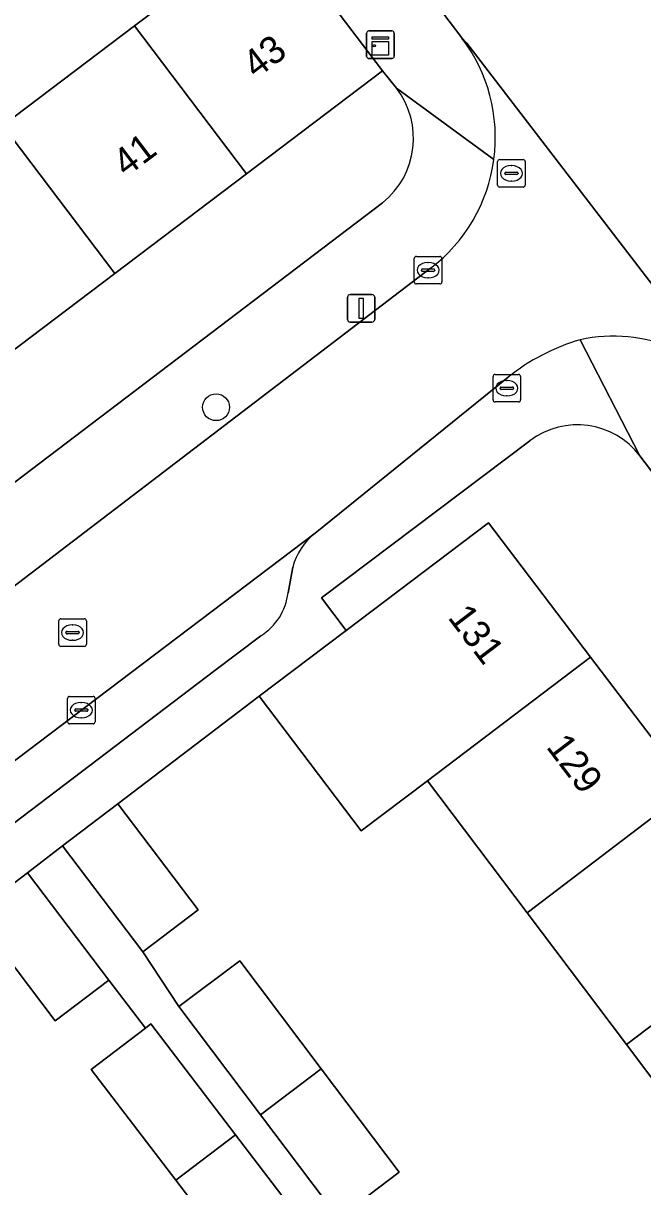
# Model space of a CAD drawing. Extents: x 160030 to 160839, y 385325 to 386450.
# Drawn here: x 160342.79 to 160365.28, y 385850.63 to 385892.89 of the extents above; entities that cross this region are included whole.
import ezdxf

# ---------------------------------------------------------------- set-up
doc = ezdxf.new("R2010")
doc.units = 0
for name, color, linetype in [('IMGEO_Boom', 7, 'Continuous'), ('IMGEO_Brandkraan', 7, 'Continuous'), ('IMGEO_Erf', 7, 'Continuous'), ('IMGEO_Kast', 7, 'Continuous'), ('IMGEO_Kolk', 7, 'Continuous'), ('IMGEO_Lichtmast', 7, 'Continuous'), ('IMGEO_Muur', 7, 'Continuous'), ('IMGEO_Pand', 7, 'Continuous'), ('IMGEO_Pand_nummerreeks', 7, 'Continuous'), ('IMGEO_Parkeervlak_open', 7, 'Continuous'), ('IMGEO_Rijbaan_lokaal_open', 7, 'Continuous'), ('IMGEO_Rioolput', 7, 'Continuous'), ('IMGEO_Voetpad_open', 7, 'Continuous')]:
    doc.layers.add(name, color=color, linetype=linetype)

msp = doc.modelspace()

# ---------------------------------------------------------------- linework, layer by layer
at = {"layer": 'IMGEO_Boom'}
msp.add_circle((160349.794, 385878.947), 0.489, dxfattribs=at)
at = {"layer": 'IMGEO_Brandkraan'}
for p, q in [((160360.014, 385887.015), (160360.014, 385887.867)), ((160360.089, 385887.941), (160360.941, 385887.941)), ((160360.502, 385887.721), (160360.527, 385887.721)), ((160361.015, 385887.867), (160361.015, 385887.015)), ((160360.273, 385887.435), (160360.273, 385887.447)), ((160360.711, 385887.398), (160360.313, 385887.398)), ((160360.316, 385887.484), (160360.714, 385887.484)), ((160360.525, 385887.161), (160360.5, 385887.161)), ((160360.757, 385887.447), (160360.757, 385887.435)), ((160360.941, 385886.941), (160360.089, 385886.941))]:
    msp.add_line(p, q, dxfattribs=at)
for points in [[(160360.014, 385887.015), (160360.014, 385887.867)], [(160360.089, 385887.941), (160360.941, 385887.941)], [(160361.015, 385887.867), (160361.015, 385887.015)], [(160360.941, 385886.941), (160360.089, 385886.941)]]:
    msp.add_lwpolyline(points, dxfattribs=at)
for centre, radius, start, end in [((160360.091, 385887.865), 0.0765, 91.552, 178.448), ((160360.091, 385887.865), 0.0765, 91.552, 178.448), ((160360.939, 385887.865), 0.0765, 1.552, 88.448), ((160360.939, 385887.865), 0.0765, 1.552, 88.448), ((160360.313, 385887.444), 0.0403, 85.8775, 175.7526), ((160360.31, 385887.434), 0.0366, 178.938, 274.7102), ((160360.714, 385887.441), 0.043, 264.8664, 352.4533), ((160360.718, 385887.446), 0.0386, 1.7309, 96.639), ((160360.091, 385887.017), 0.0765, 181.552, 268.448), ((160360.091, 385887.017), 0.0765, 181.552, 268.448), ((160360.939, 385887.017), 0.0765, 271.552, 358.448), ((160360.939, 385887.017), 0.0765, 271.552, 358.448)]:
    msp.add_arc(centre, radius, start, end, dxfattribs=at)
for centre, major_axis, ratio, start_param, end_param in [((160360.501, 385887.441), (-0.387, 0.002), 0.722429, 4.712389, 7.853982), ((160360.526, 385887.441), (-0.39, 0.002), 0.717154, 1.570796, 4.712389)]:
    msp.add_ellipse(centre, major_axis=major_axis, ratio=ratio, start_param=start_param, end_param=end_param, dxfattribs=at)
at = {"layer": 'IMGEO_Erf'}
for points in [[(160294.063, 385852.843), (160298.997, 385856.578), (160303.779, 385860.2), (160308.563, 385863.822), (160313.347, 385867.444), (160318.13, 385871.066), (160322.914, 385874.688), (160327.697, 385878.309), (160332.481, 385881.931), (160337.264, 385885.553), (160335.354, 385888.075), (160340.138, 385891.697), (160342.048, 385889.175), (160346.831, 385892.796), (160351.765, 385896.532)], [(160356.339, 385890.539), (160355.831, 385891.162), (160350.897, 385887.426), (160346.114, 385883.805), (160341.33, 385880.183), (160336.547, 385876.561), (160331.763, 385872.939), (160326.98, 385869.318), (160322.196, 385865.696), (160317.412, 385862.073), (160312.629, 385858.452), (160307.845, 385854.83), (160303.062, 385851.208), (160298.129, 385847.473), (160300.518, 385844.329), (160355.835, 385886.372)], [(160361.189, 385877.731), (160353.622, 385872.023), (160354.522, 385870.841), (160359.681, 385874.747), (160363.386, 385869.872), (160367.015, 385865.095), (160370.645, 385860.318), (160374.276, 385855.54), (160377.906, 385850.763), (160381.536, 385845.985), (160385.166, 385841.208), (160388.796, 385836.431), (160392.426, 385831.653), (160396.056, 385826.876), (160399.687, 385822.098), (160403.316, 385817.321)], [(160425.684, 385797.636), (160365.182, 385877.181)], [(160368.302, 385851), (160364.692, 385855.793), (160361.083, 385860.586), (160357.473, 385865.379), (160355.064, 385863.555), (160351.36, 385868.446), (160346.224, 385864.537), (160349.141, 385860.685), (160347.132, 385859.164), (160348.447, 385857.175), (160350.654, 385858.838), (160353.608, 385854.917), (160356.441, 385851.157), (160354.234, 385849.495), (160355.644, 385847.541), (160357.933, 385849.297), (160360.866, 385845.359), (160363.656, 385841.612), (160361.48, 385839.942), (160362.994, 385838.058), (160365.235, 385839.759), (160366.479, 385838.119)], [(160351.187, 385847.126), (160348.331, 385850.871), (160345.262, 385854.895), (160347.23, 385856.396), (160345.903, 385858.136), (160343.947, 385856.654), (160340.997, 385860.55), (160332.936, 385854.418), (160336.632, 385849.537)]]:
    msp.add_lwpolyline(points, dxfattribs=at)
for centre, radius, start, end in [((160353.962, 385888.713), 2.998, 308.6711, 37.536), ((160362.909, 385875.449), 2.857, 37.3033, 127.0114)]:
    msp.add_arc(centre, radius, start, end, dxfattribs=at)
at = {"layer": 'IMGEO_Kast'}
for p, q in [((160355.259, 385891.688), (160355.259, 385892.529)), ((160355.259, 385892.529), (160355.259, 385891.688)), ((160355.334, 385892.613), (160356.175, 385892.613)), ((160356.175, 385892.613), (160355.334, 385892.613)), ((160356.259, 385892.538), (160356.259, 385891.697)), ((160356.259, 385891.697), (160356.259, 385892.538)), ((160356.184, 385891.613), (160355.343, 385891.613)), ((160355.343, 385891.613), (160356.184, 385891.613))]:
    msp.add_line(p, q, dxfattribs=at)
for points in [[(160355.454, 385892.403), (160356.054, 385892.403), (160356.054, 385892.318), (160355.454, 385892.318), (160355.454, 385892.403)], [(160355.454, 385892.228), (160356.054, 385892.228), (160356.054, 385891.739), (160355.454, 385891.739), (160355.454, 385892.228)]]:
    msp.add_lwpolyline(points, dxfattribs=at)
msp.add_circle((160355.538, 385892.077), 0.0377, dxfattribs=at)
for centre, start, end in [((160355.337, 385892.535), 92.4484, 184.2845), ((160355.337, 385892.535), 92.4484, 184.2845), ((160356.181, 385892.535), 2.4484, 94.2845), ((160356.181, 385892.535), 2.4484, 94.2845), ((160355.337, 385891.691), 182.4484, 274.2845), ((160355.337, 385891.691), 182.4484, 274.2845), ((160356.181, 385891.691), 272.4484, 4.2845), ((160356.181, 385891.691), 272.4484, 4.2845)]:
    msp.add_arc(centre, 0.0779, start, end, dxfattribs=at)
at = {"layer": 'IMGEO_Kolk'}
for p, q in [((160356.989, 385883.498), (160356.989, 385884.35)), ((160357.064, 385884.424), (160357.916, 385884.424)), ((160357.477, 385884.204), (160357.502, 385884.204)), ((160357.99, 385884.35), (160357.99, 385883.498)), ((160357.248, 385883.918), (160357.248, 385883.93)), ((160357.686, 385883.881), (160357.288, 385883.881)), ((160357.291, 385883.967), (160357.689, 385883.967)), ((160357.732, 385883.93), (160357.732, 385883.918)), ((160357.916, 385883.424), (160357.064, 385883.424)), ((160357.5, 385883.644), (160357.475, 385883.644)), ((160359.847, 385879.211), (160359.847, 385880.063)), ((160359.922, 385880.137), (160360.774, 385880.137)), ((160360.848, 385880.063), (160360.848, 385879.211)), ((160360.106, 385879.631), (160360.106, 385879.643)), ((160360.544, 385879.594), (160360.146, 385879.594)), ((160360.149, 385879.68), (160360.547, 385879.68)), ((160360.335, 385879.917), (160360.36, 385879.917)), ((160360.59, 385879.643), (160360.59, 385879.631)), ((160360.774, 385879.137), (160359.922, 385879.137)), ((160360.358, 385879.357), (160360.333, 385879.357)), ((160344.401, 385867.517), (160344.401, 385868.369)), ((160344.476, 385868.443), (160345.328, 385868.443)), ((160344.889, 385868.223), (160344.914, 385868.223)), ((160345.402, 385868.369), (160345.402, 385867.517)), ((160344.66, 385867.937), (160344.66, 385867.949)), ((160345.098, 385867.9), (160344.7, 385867.9)), ((160344.703, 385867.986), (160345.101, 385867.986)), ((160345.144, 385867.949), (160345.144, 385867.937)), ((160345.328, 385867.443), (160344.476, 385867.443)), ((160344.912, 385867.663), (160344.887, 385867.663))]:
    msp.add_line(p, q, dxfattribs=at)
for points in [[(160356.989, 385883.498), (160356.989, 385884.35)], [(160357.064, 385884.424), (160357.916, 385884.424)], [(160357.99, 385884.35), (160357.99, 385883.498)], [(160357.916, 385883.424), (160357.064, 385883.424)], [(160359.847, 385879.211), (160359.847, 385880.063)], [(160359.922, 385880.137), (160360.774, 385880.137)], [(160360.848, 385880.063), (160360.848, 385879.211)], [(160360.774, 385879.137), (160359.922, 385879.137)], [(160344.401, 385867.517), (160344.401, 385868.369)], [(160344.476, 385868.443), (160345.328, 385868.443)], [(160345.402, 385868.369), (160345.402, 385867.517)], [(160345.328, 385867.443), (160344.476, 385867.443)]]:
    msp.add_lwpolyline(points, dxfattribs=at)
for centre, radius, start, end in [((160357.066, 385884.348), 0.0765, 91.552, 178.448), ((160357.066, 385884.348), 0.0765, 91.552, 178.448), ((160357.914, 385884.348), 0.0765, 1.552, 88.448), ((160357.914, 385884.348), 0.0765, 1.552, 88.448), ((160357.288, 385883.927), 0.0403, 85.8775, 175.7526), ((160357.285, 385883.917), 0.0366, 178.938, 274.7102), ((160357.689, 385883.924), 0.043, 264.8664, 352.4533), ((160357.693, 385883.929), 0.0386, 1.7309, 96.639), ((160357.066, 385883.5), 0.0765, 181.552, 268.448), ((160357.066, 385883.5), 0.0765, 181.552, 268.448), ((160357.914, 385883.5), 0.0765, 271.552, 358.448), ((160357.914, 385883.5), 0.0765, 271.552, 358.448), ((160359.924, 385880.061), 0.0765, 91.552, 178.448), ((160359.924, 385880.061), 0.0765, 91.552, 178.448), ((160360.772, 385880.061), 0.0765, 1.552, 88.448), ((160360.772, 385880.061), 0.0765, 1.552, 88.448), ((160360.146, 385879.64), 0.0403, 85.8775, 175.7526), ((160360.143, 385879.63), 0.0366, 178.938, 274.7102), ((160360.547, 385879.637), 0.043, 264.8664, 352.4533), ((160360.551, 385879.642), 0.0386, 1.7309, 96.639), ((160359.924, 385879.213), 0.0765, 181.552, 268.448), ((160359.924, 385879.213), 0.0765, 181.552, 268.448), ((160360.772, 385879.213), 0.0765, 271.552, 358.448), ((160360.772, 385879.213), 0.0765, 271.552, 358.448), ((160344.478, 385868.367), 0.0765, 91.552, 178.448), ((160344.478, 385868.367), 0.0765, 91.552, 178.448), ((160345.326, 385868.367), 0.0765, 1.552, 88.448), ((160345.326, 385868.367), 0.0765, 1.552, 88.448), ((160344.7, 385867.946), 0.0403, 85.8775, 175.7526), ((160344.697, 385867.936), 0.0366, 178.938, 274.7102), ((160345.101, 385867.943), 0.043, 264.8664, 352.4533), ((160345.105, 385867.948), 0.0386, 1.7309, 96.639), ((160344.478, 385867.519), 0.0765, 181.552, 268.448), ((160344.478, 385867.519), 0.0765, 181.552, 268.448), ((160345.326, 385867.519), 0.0765, 271.552, 358.448), ((160345.326, 385867.519), 0.0765, 271.552, 358.448)]:
    msp.add_arc(centre, radius, start, end, dxfattribs=at)
for centre, major_axis, ratio, start_param, end_param in [((160357.476, 385883.924), (-0.387, 0.002), 0.722429, 4.712389, 7.853982), ((160357.501, 385883.924), (-0.39, 0.002), 0.717154, 1.570796, 4.712389), ((160360.334, 385879.637), (-0.387, 0.002), 0.722429, 4.712389, 7.853982), ((160360.359, 385879.637), (-0.39, 0.002), 0.717154, 1.570796, 4.712389), ((160344.888, 385867.943), (-0.387, 0.002), 0.722429, 4.712389, 7.853982), ((160344.913, 385867.943), (-0.39, 0.002), 0.717154, 1.570796, 4.712389)]:
    msp.add_ellipse(centre, major_axis=major_axis, ratio=ratio, start_param=start_param, end_param=end_param, dxfattribs=at)
at = {"layer": 'IMGEO_Lichtmast'}
for p, q in [((160354.563, 385882.138), (160354.563, 385882.938)), ((160354.563, 385882.938), (160354.563, 385882.138)), ((160354.663, 385883.038), (160355.453, 385883.038)), ((160355.453, 385883.038), (160354.663, 385883.038)), ((160355.553, 385882.938), (160355.553, 385882.138)), ((160355.553, 385882.138), (160355.553, 385882.938)), ((160355.453, 385882.038), (160354.663, 385882.038)), ((160354.663, 385882.038), (160355.453, 385882.038))]:
    msp.add_line(p, q, dxfattribs=at)
msp.add_lwpolyline([(160354.983, 385882.913), (160355.133, 385882.913), (160355.133, 385882.163), (160354.983, 385882.163), (160354.983, 385882.913)], dxfattribs=at)
for centre, start, end in [((160354.663, 385882.938), 90, 180), ((160354.663, 385882.938), 90, 180), ((160355.453, 385882.938), 0, 90), ((160355.453, 385882.938), 360, 90), ((160354.663, 385882.138), 180, 270), ((160354.663, 385882.138), 180, 270), ((160355.453, 385882.138), 270, 0), ((160355.453, 385882.138), 270, 0)]:
    msp.add_arc(centre, 0.1, start, end, dxfattribs=at)
at = {"layer": 'IMGEO_Muur'}
msp.add_lwpolyline([(160346.224, 385864.537), (160351.36, 385868.446)], dxfattribs=at)
at = {"layer": 'IMGEO_Pand'}
for points in [[(160351.765, 385896.532), (160346.831, 385892.796), (160350.897, 385887.426), (160355.831, 385891.162)], [(160346.831, 385892.796), (160342.048, 385889.175), (160346.114, 385883.805), (160350.897, 385887.426)], [(160342.048, 385889.175), (160340.138, 385891.697), (160335.354, 385888.075), (160337.264, 385885.553), (160341.33, 385880.183), (160346.114, 385883.805)], [(160357.473, 385865.379), (160363.386, 385869.872), (160359.681, 385874.747), (160354.522, 385870.841), (160353.782, 385870.28), (160351.36, 385868.446), (160355.064, 385863.555)], [(160367.015, 385865.095), (160363.386, 385869.872), (160357.473, 385865.379), (160361.083, 385860.586)], [(160370.645, 385860.318), (160367.015, 385865.095), (160361.083, 385860.586), (160364.692, 385855.793)], [(160344.216, 385863.016), (160347.132, 385859.164), (160349.141, 385860.685), (160346.224, 385864.537)], [(160340.997, 385860.55), (160343.947, 385856.654), (160345.903, 385858.136), (160342.953, 385862.032)], [(160364.692, 385855.793), (160368.302, 385851), (160374.276, 385855.54), (160370.645, 385860.318)], [(160350.654, 385858.838), (160348.447, 385857.175), (160351.409, 385853.245), (160353.608, 385854.917)], [(160347.426, 385856.545), (160347.23, 385856.396), (160345.262, 385854.895), (160348.331, 385850.871), (160350.5, 385852.513)], [(160351.409, 385853.245), (160354.234, 385849.495), (160356.441, 385851.157), (160353.608, 385854.917)], [(160348.331, 385850.871), (160351.187, 385847.126), (160353.35, 385848.776), (160350.5, 385852.513)]]:
    msp.add_lwpolyline(points, close=True, dxfattribs=at)
at = {"layer": 'IMGEO_Parkeervlak_open'}
for points in [[(160353.387, 385874.369), (160336.283, 385861.419), (160326.328, 385853.868)], [(160352.408, 385872.206), (160352.578, 385873.139)], [(160349.751, 385869.377), (160351.421, 385870.644)], [(160329.781, 385854.21), (160336.673, 385859.456), (160349.751, 385869.377)]]:
    msp.add_lwpolyline(points, dxfattribs=at)
for centre, radius, start, end in [((160354.865, 385872.516), 2.371, 128.5764, 164.7559), ((160350.273, 385872.462), 2.15, 302.2652, 353.1587)]:
    msp.add_arc(centre, radius, start, end, dxfattribs=at)
at = {"layer": 'IMGEO_Rijbaan_lokaal_open'}
for points in [[(160332.303, 385927.233), (160345.107, 385910.299), (160358.716, 385892.358), (160358.891, 385892.166), (160368.75, 385879.341), (160369.011, 385878.899), (160390.932, 385850.046), (160400.824, 385837.058), (160410.888, 385823.854), (160427.481, 385801.96), (160433.017, 385806.06), (160432.182, 385807.154), (160431.721, 385807.759), (160424.163, 385817.668), (160408.384, 385838.431), (160407.664, 385839.378)], [(160369.011, 385878.899), (160368.75, 385879.341), (160358.891, 385892.166), (160358.716, 385892.358)], [(160357.581, 385883.992), (160334.468, 385866.348), (160310.316, 385848.008)], [(160316.136, 385846.137), (160322.717, 385851.129), (160326.328, 385853.868), (160336.283, 385861.419), (160353.387, 385874.369), (160360.393, 385880.034)]]:
    msp.add_lwpolyline(points, dxfattribs=at)
for centre, radius, start, end in [((160353.951, 385888.744), 5.98, 352.2714, 37.1761), ((160353.955, 385888.742), 5.976, 307.3552, 352.2836), ((160365.116, 385874.144), 7.55, 106.2089, 128.729), ((160364.227, 385875.857), 5.67, 32.4528, 102.4024)]:
    msp.add_arc(centre, radius, start, end, dxfattribs=at)
at = {"layer": 'IMGEO_Rioolput'}
for p, q in [((160344.083, 385870.334), (160344.083, 385871.186)), ((160344.158, 385871.26), (160345.01, 385871.26)), ((160345.084, 385871.186), (160345.084, 385870.334)), ((160344.342, 385870.754), (160344.342, 385870.766)), ((160344.78, 385870.717), (160344.382, 385870.717)), ((160344.385, 385870.803), (160344.783, 385870.803)), ((160344.571, 385871.04), (160344.596, 385871.04)), ((160344.826, 385870.766), (160344.826, 385870.754)), ((160345.01, 385870.26), (160344.158, 385870.26)), ((160344.594, 385870.48), (160344.569, 385870.48))]:
    msp.add_line(p, q, dxfattribs=at)
for points in [[(160344.083, 385870.334), (160344.083, 385871.186)], [(160344.158, 385871.26), (160345.01, 385871.26)], [(160345.084, 385871.186), (160345.084, 385870.334)], [(160345.01, 385870.26), (160344.158, 385870.26)]]:
    msp.add_lwpolyline(points, dxfattribs=at)
for centre, radius, start, end in [((160344.16, 385871.184), 0.0765, 91.552, 178.448), ((160344.16, 385871.184), 0.0765, 91.552, 178.448), ((160345.008, 385871.184), 0.0765, 1.552, 88.448), ((160345.008, 385871.184), 0.0765, 1.552, 88.448), ((160344.382, 385870.763), 0.0403, 85.8775, 175.7526), ((160344.379, 385870.753), 0.0366, 178.938, 274.7102), ((160344.783, 385870.76), 0.043, 264.8664, 352.4533), ((160344.787, 385870.765), 0.0386, 1.7309, 96.639), ((160344.16, 385870.336), 0.0765, 181.552, 268.448), ((160344.16, 385870.336), 0.0765, 181.552, 268.448), ((160345.008, 385870.336), 0.0765, 271.552, 358.448), ((160345.008, 385870.336), 0.0765, 271.552, 358.448)]:
    msp.add_arc(centre, radius, start, end, dxfattribs=at)
for centre, major_axis, ratio, start_param, end_param in [((160344.57, 385870.76), (-0.387, 0.002), 0.722429, 4.712389, 7.853982), ((160344.595, 385870.76), (-0.39, 0.002), 0.717154, 1.570796, 4.712389)]:
    msp.add_ellipse(centre, major_axis=major_axis, ratio=ratio, start_param=start_param, end_param=end_param, dxfattribs=at)
at = {"layer": 'IMGEO_Voetpad_open'}
for points in [[(160329.973, 385925.286), (160331.526, 385923.244), (160335.523, 385917.965), (160341.653, 385909.841), (160343.174, 385907.832), (160344.055, 385906.708), (160345.638, 385904.618), (160351.765, 385896.532), (160355.831, 385891.162), (160356.339, 385890.539), (160359.877, 385887.94)], [(160358.716, 385892.358), (160345.107, 385910.299)], [(160359.877, 385887.94), (160356.339, 385890.539)], [(160355.835, 385886.372), (160300.518, 385844.329), (160299.39, 385843.472), (160301.695, 385840.441), (160302.585, 385841.09), (160333.469, 385800.262)], [(160310.316, 385848.008), (160334.468, 385866.348), (160357.581, 385883.992)], [(160365.182, 385877.181), (160363.009, 385881.394)], [(160363.009, 385881.394), (160365.182, 385877.181), (160425.684, 385797.636)], [(160360.393, 385880.034), (160353.387, 385874.369)], [(160326.797, 385849.728), (160327.586, 385850.367), (160332.936, 385854.418), (160340.997, 385860.55), (160342.953, 385862.032), (160344.216, 385863.016), (160346.224, 385864.537), (160351.36, 385868.446), (160353.782, 385870.28), (160354.522, 385870.841), (160353.622, 385872.023), (160361.189, 385877.731)], [(160352.578, 385873.139), (160352.408, 385872.206)], [(160351.421, 385870.644), (160349.751, 385869.377), (160336.673, 385859.456), (160329.781, 385854.21)], [(160365.957, 385834.154), (160362.994, 385838.058), (160361.48, 385839.942), (160358.628, 385843.658), (160355.644, 385847.541), (160354.234, 385849.495), (160351.409, 385853.245), (160348.447, 385857.175), (160347.132, 385859.164), (160344.216, 385863.016), (160342.953, 385862.032), (160345.903, 385858.136), (160347.23, 385856.396), (160347.426, 385856.545), (160350.5, 385852.513), (160353.35, 385848.776), (160354.686, 385846.989), (160357.76, 385842.957), (160360.61, 385839.22), (160361.946, 385837.433), (160365.02, 385833.401), (160367.87, 385829.664)]]:
    msp.add_lwpolyline(points, dxfattribs=at)
for centre, radius, start, end in [((160353.951, 385888.744), 5.98, 352.2714, 37.1761), ((160353.962, 385888.713), 2.998, 308.6711, 37.536), ((160353.955, 385888.742), 5.976, 307.3552, 352.2836), ((160365.116, 385874.144), 7.55, 106.2089, 128.729), ((160364.227, 385875.857), 5.67, 32.4528, 102.4024), ((160362.909, 385875.449), 2.857, 37.3033, 127.0114), ((160354.865, 385872.516), 2.371, 128.5764, 164.7559), ((160350.273, 385872.462), 2.15, 302.2652, 353.1587)]:
    msp.add_arc(centre, radius, start, end, dxfattribs=at)

# ---------------------------------------------------------------- texts
at = {"layer": 'IMGEO_Pand_nummerreeks'}
for s, rotation, p in [('43', 37.1311, (160351.246, 385890.852)), ('41', 37.1311, (160346.529, 385887.28)), ('131', 307.2297, (160358.179, 385871.303)), ('129', 307.2297, (160361.749, 385866.603))]:
    msp.add_text(s, height=1, rotation=rotation, dxfattribs=at).set_placement(p)

doc.saveas('drawing.dxf')
